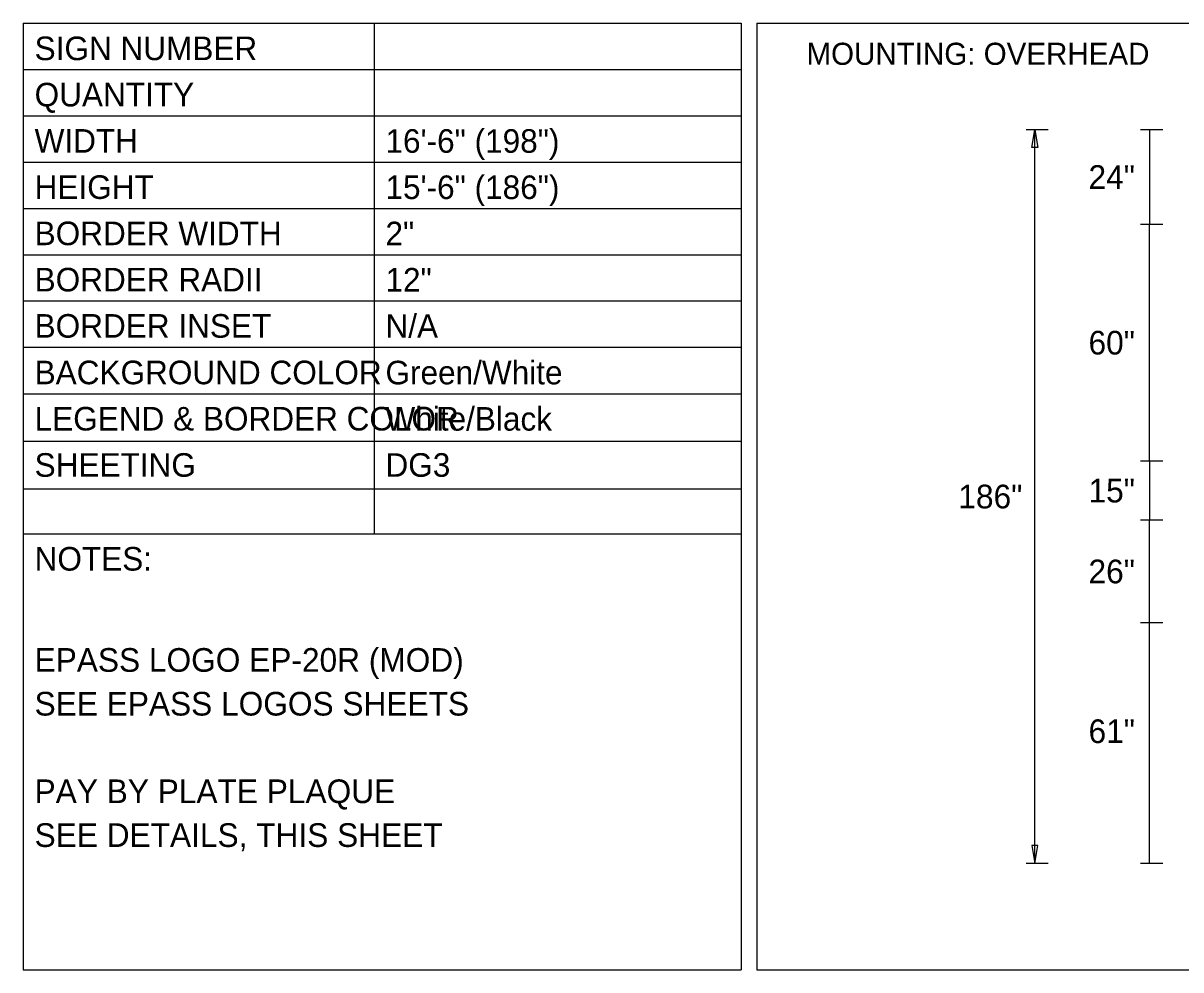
# Model space of a CAD drawing. Extents: x 10268312 to 10268472, y 2142583 to 2142688.
# Drawn here: x 10268318.48 to 10268355.16, y 2142657.53 to 2142687.53 of the extents above; entities that cross this region are included whole.
import ezdxf

# ---------------------------------------------------------------- set-up
doc = ezdxf.new("R2010")
doc.units = 0
for name, color, linetype in [('GSDims', 7, 'Continuous'), ('SumBoxLines_dp', 7, 'Continuous'), ('TextMisc', 7, 'Continuous')]:
    doc.layers.add(name, color=color, linetype=linetype)

msp = doc.modelspace()

# ---------------------------------------------------------------- linework, layer by layer
at = {"layer": 'GSDims'}
for p, q in [((10268350.961, 2142684.156), (10268350.258, 2142684.156)), ((10268350.539, 2142660.906), (10268350.539, 2142684.156)), ((10268354.588, 2142684.156), (10268353.885, 2142684.156)), ((10268354.166, 2142684.156), (10268354.166, 2142681.156)), ((10268354.588, 2142681.156), (10268353.885, 2142681.156)), ((10268354.166, 2142673.656), (10268354.166, 2142681.156)), ((10268354.588, 2142673.656), (10268353.885, 2142673.656)), ((10268354.166, 2142673.656), (10268354.166, 2142671.781)), ((10268354.588, 2142671.781), (10268353.885, 2142671.781)), ((10268354.166, 2142668.531), (10268354.166, 2142671.781)), ((10268354.588, 2142668.531), (10268353.885, 2142668.531)), ((10268354.166, 2142660.906), (10268354.166, 2142668.531)), ((10268350.961, 2142660.906), (10268350.258, 2142660.906)), ((10268354.588, 2142660.906), (10268353.885, 2142660.906))]:
    msp.add_line(p, q, dxfattribs=at)
for points in [[(10268350.539, 2142684.156), (10268350.633, 2142683.594), (10268350.446, 2142683.594)], [(10268350.539, 2142660.906), (10268350.633, 2142661.469), (10268350.446, 2142661.469)]]:
    msp.add_lwpolyline(points, close=True, dxfattribs=at)
at = {"layer": 'SumBoxLines_dp'}
for p, q in [((10268318.48, 2142687.532), (10268318.48, 2142657.532)), ((10268318.48, 2142687.532), (10268341.23, 2142687.532)), ((10268329.598, 2142687.528), (10268329.598, 2142671.345)), ((10268341.23, 2142687.532), (10268341.23, 2142657.532)), ((10268341.73, 2142687.532), (10268341.73, 2142657.532)), ((10268341.73, 2142687.532), (10268393.98, 2142687.532)), ((10268318.48, 2142686.066), (10268341.23, 2142686.066)), ((10268318.48, 2142684.59), (10268341.23, 2142684.59)), ((10268318.48, 2142683.125), (10268341.23, 2142683.125)), ((10268318.48, 2142681.659), (10268341.23, 2142681.659)), ((10268318.48, 2142680.193), (10268341.23, 2142680.193)), ((10268318.48, 2142678.727), (10268341.23, 2142678.727)), ((10268318.48, 2142677.261), (10268341.23, 2142677.261)), ((10268318.48, 2142675.786), (10268341.23, 2142675.786)), ((10268318.48, 2142674.281), (10268341.23, 2142674.281)), ((10268318.48, 2142672.776), (10268341.23, 2142672.776)), ((10268318.478, 2142671.345), (10268341.229, 2142671.345)), ((10268318.48, 2142657.532), (10268341.23, 2142657.532)), ((10268341.73, 2142657.532), (10268393.98, 2142657.532))]:
    msp.add_line(p, q, dxfattribs=at)

# ---------------------------------------------------------------- texts
at = {"layer": 'GSDims'}
for s, height, p in [('MOUNTING: OVERHEAD ', 0.7, (10268343.3, 2142686.211)), ('24"', 0.75, (10268352.238, 2142682.281)), ('60"', 0.75, (10268352.238, 2142677.031)), ('15"', 0.75, (10268352.238, 2142672.344)), ('26"', 0.75, (10268352.238, 2142669.781)), ('61"', 0.75, (10268352.238, 2142664.719))]:
    msp.add_text(s, height=height, dxfattribs=at).set_placement(p)
msp.add_text('186"', height=0.75, rotation=360, dxfattribs=at).set_placement((10268348.113, 2142672.156))
at = {"layer": 'TextMisc'}
for s, height, p in [('SIGN NUMBER', 0.74756, (10268318.841, 2142686.359)), ('QUANTITY', 0.7476, (10268318.841, 2142684.893)), ('16\'-6" (198")', 0.74756, (10268329.959, 2142683.424)), ('WIDTH', 0.7476, (10268318.841, 2142683.427)), ('15\'-6" (186")', 0.74756, (10268329.959, 2142681.958)), ('HEIGHT', 0.7476, (10268318.841, 2142681.962)), ('BORDER WIDTH', 0.74756, (10268318.841, 2142680.496)), ('2"', 0.7476, (10268329.959, 2142680.492)), ('BORDER RADII', 0.74756, (10268318.841, 2142679.03)), ('12"', 0.7476, (10268329.959, 2142679.026)), ('BORDER INSET', 0.74756, (10268318.841, 2142677.564)), ('N/A', 0.7476, (10268329.959, 2142677.561)), ('Green/White', 0.74756, (10268329.959, 2142676.085)), ('BACKGROUND COLOR', 0.74756, (10268318.841, 2142676.089)), ('White/Black', 0.74756, (10268329.959, 2142674.619)), ('LEGEND & BORDER COLOR', 0.74756, (10268318.841, 2142674.623)), ('SHEETING', 0.7476, (10268318.841, 2142673.157)), ('DG3', 0.7476, (10268329.959, 2142673.157)), ('NOTES:', 0.7476, (10268318.84, 2142670.184)), ('EPASS LOGO EP-20R (MOD)', 0.75, (10268318.84, 2142666.977)), ('SEE EPASS LOGOS SHEETS', 0.75, (10268318.84, 2142665.59)), ('PAY BY PLATE PLAQUE', 0.75, (10268318.84, 2142662.815)), ('SEE DETAILS, THIS SHEET', 0.75, (10268318.84, 2142661.427))]:
    msp.add_text(s, height=height, dxfattribs=at).set_placement(p)

doc.saveas('drawing.dxf')
